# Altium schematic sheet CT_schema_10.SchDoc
size 385 x 278 mm
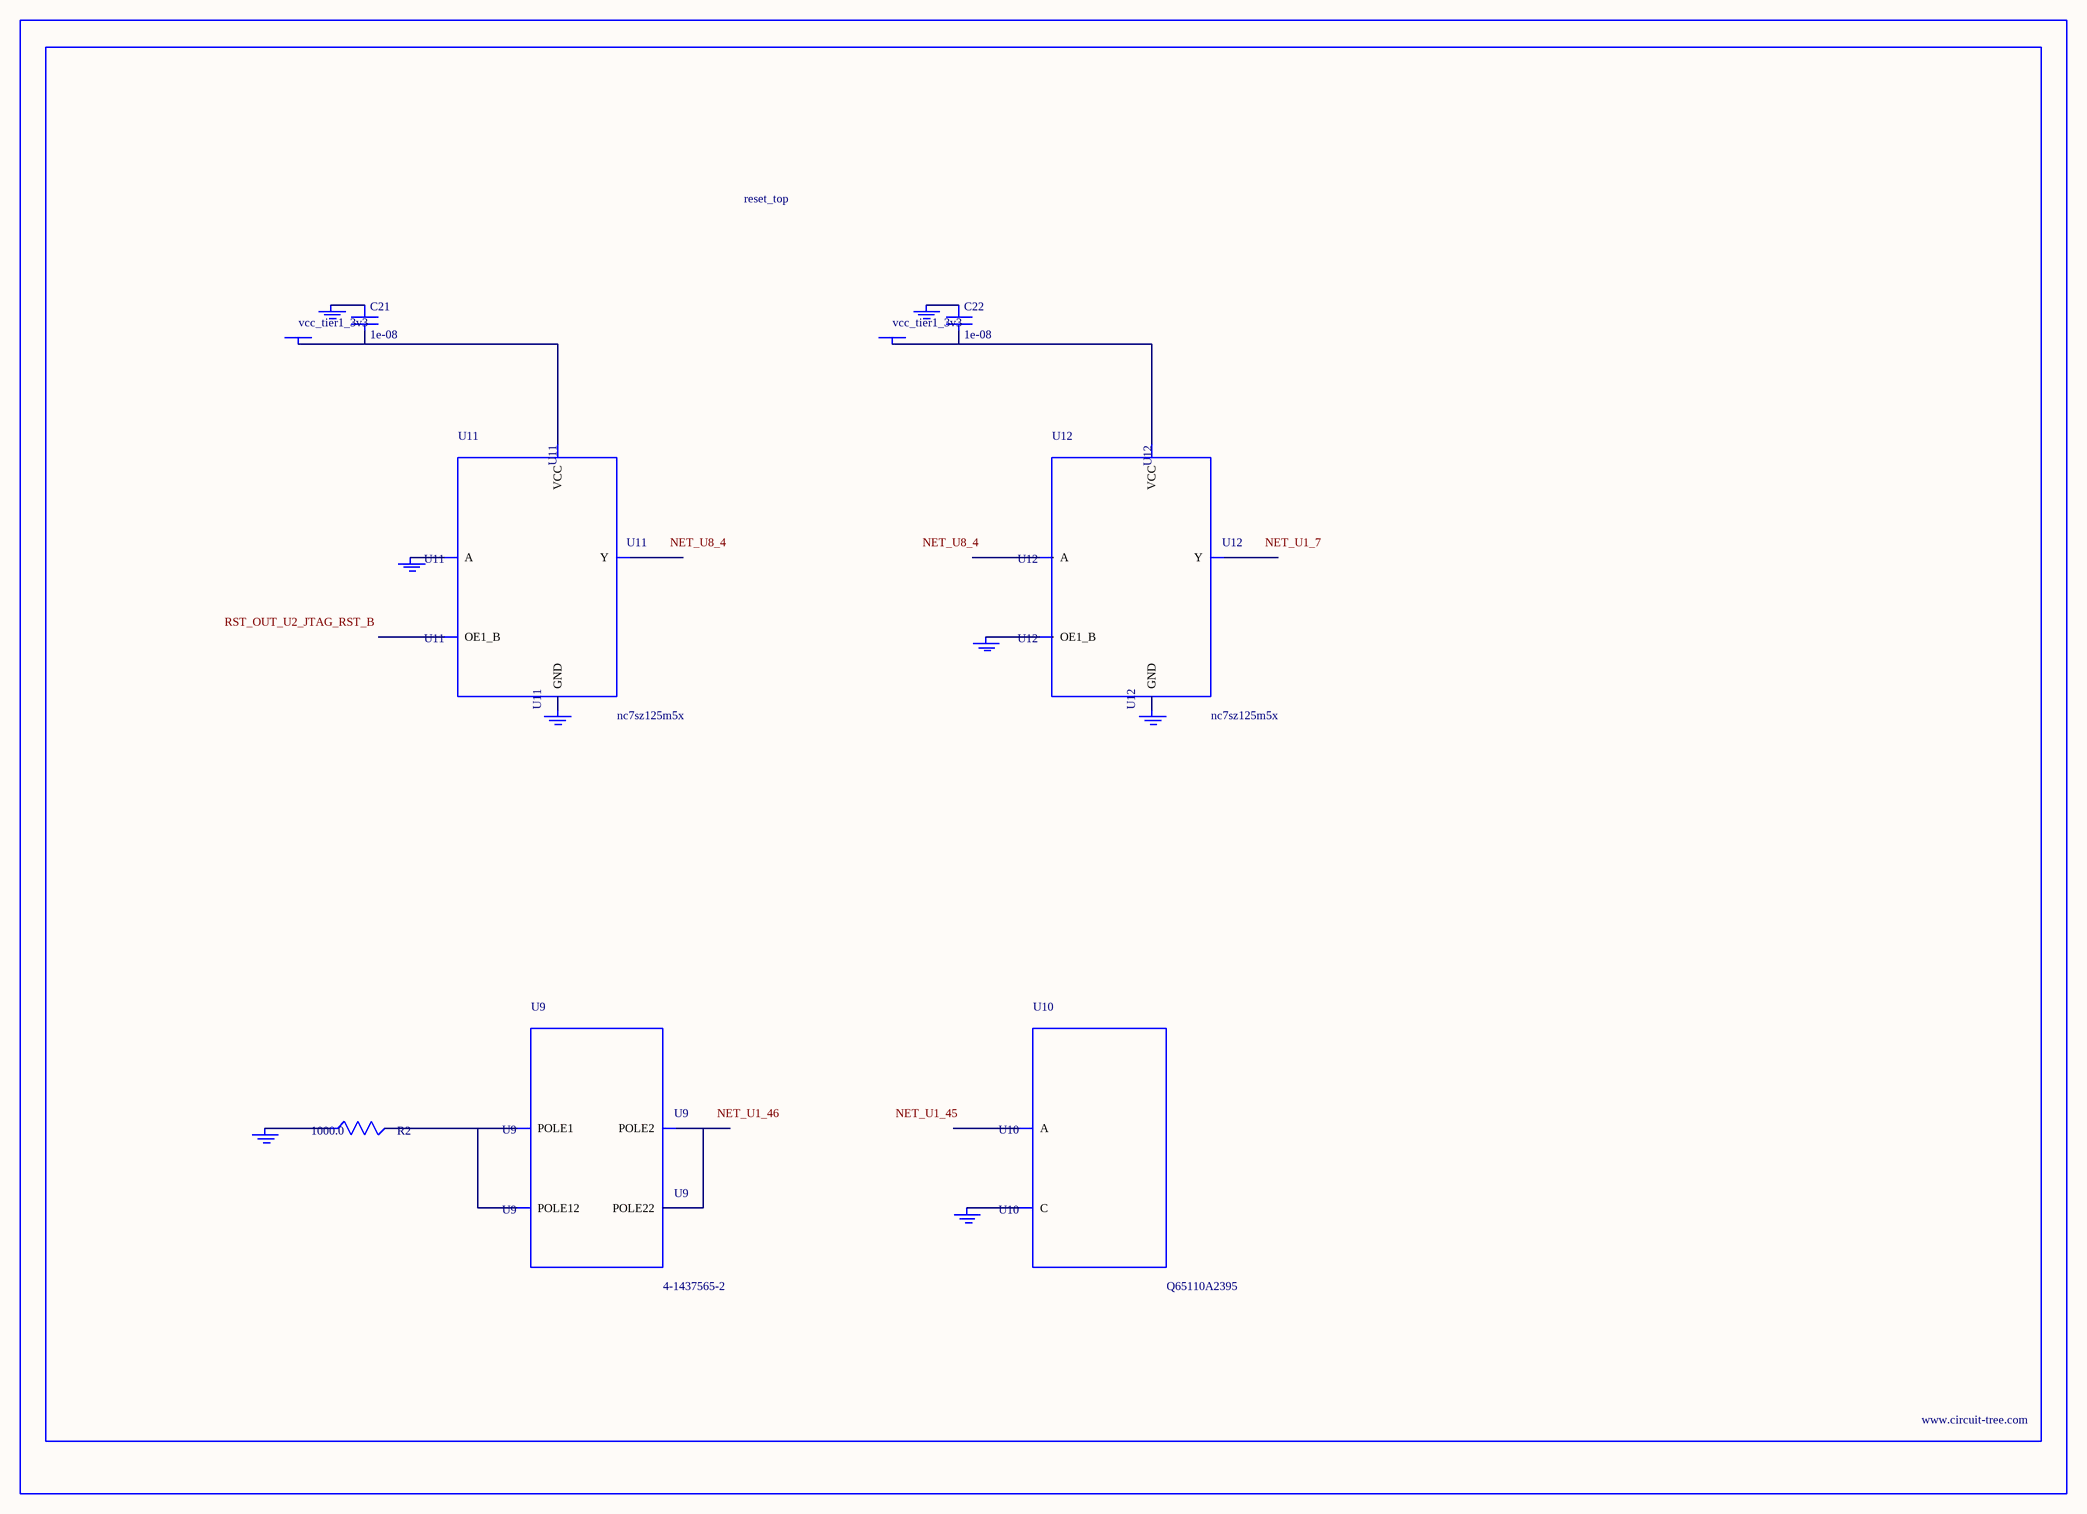
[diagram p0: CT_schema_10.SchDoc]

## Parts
BORDER9  (no value)
C21  1e-08  [C0402]
C22  1e-08  [C0402]
GND_INSTANCE_9_0  (no value)
GND_INSTANCE_9_1  (no value)
GND_INSTANCE_9_2  (no value)
GND_INSTANCE_9_3  (no value)
GND_INSTANCE_9_4  (no value)
GND_INSTANCE_9_5  (no value)
GND_INSTANCE_9_6  (no value)
GND_INSTANCE_9_7  (no value)
POWER_INSTANCE_9_0  vcc_tier1_3v3
POWER_INSTANCE_9_1  vcc_tier1_3v3
R2  1000.0  [R0603]
U9  4-1437565-2  [SW_4-1437565-2]
U10  Q65110A2395  [LGM67K-G1J2-24-Z]
U11  nc7sz125m5x  [NC7SZ125M5X]
U12  nc7sz125m5x  [NC7SZ125M5X]

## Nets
NetC21_1: C21.1 GND_INSTANCE_9_2.0(GND)
NetC21_2: C21.2 POWER_INSTANCE_9_0.0(PWR) U11.5(VCC)
NetC22_1: C22.1 GND_INSTANCE_9_5.0(GND)
NetC22_2: C22.2 POWER_INSTANCE_9_1.0(PWR) U12.5(VCC)
NetGND_INSTANCE_9_0_0: GND_INSTANCE_9_0.0(GND) R2.1
NetGND_INSTANCE_9_1_0: GND_INSTANCE_9_1.0(GND) U10.C
NetGND_INSTANCE_9_3_0: GND_INSTANCE_9_3.0(GND) U11.2(A)
NetGND_INSTANCE_9_4_0: GND_INSTANCE_9_4.0(GND) U11.3(GND)
NetGND_INSTANCE_9_6_0: GND_INSTANCE_9_6.0(GND) U12.1(OE1_B)
NetGND_INSTANCE_9_7_0: GND_INSTANCE_9_7.0(GND) U12.3(GND)
NetR2_2: R2.2 U9.1(POLE1) U9.2(POLE12)
NetU9_3: U9.3(POLE2) U9.4(POLE22)

Not connected (* = marked no-connect by the designer): U10 A; U11 1(OE1_B) 4(Y); U12 2(A) 4(Y)

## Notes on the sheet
- Labels drawn without touching a wire or pin: NET_U1_7, NET_U1_45, NET_U1_46, NET_U8_4, RST_OUT_U2_JTAG_RST_B

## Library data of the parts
BORDER9 = BORDER_PAGE9
C21 C22 = C0402C103K3RAC
GND_INSTANCE_9_0-GND_INSTANCE_9_7 = GND
POWER_INSTANCE_9_0 POWER_INSTANCE_9_1 = PWR
R2 = RC0603JR-071KL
